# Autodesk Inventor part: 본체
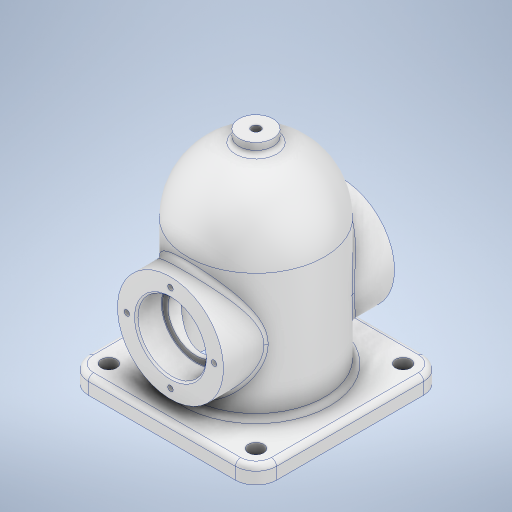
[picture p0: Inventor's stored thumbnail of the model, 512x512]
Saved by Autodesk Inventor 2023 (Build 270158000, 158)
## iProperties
Created: 2025-04
Part Number: 본체
Material: 알루미늄 6061
Document SubType Name: Modeling
Designer: User
Density: 2.7 g/cm^3
Appearance: 알루미늄 - 평지
Mass: 865.907 g
Surface Area: 800.754 cm^2
Volume: 320.706 cm^3
Author: User
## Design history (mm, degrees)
sketch "스케치1"
  geometry: C1 r 31 at (0, 0); 1 further point
  constraints: 1 centre point, 1 coincident
  dimensions: "d0" = 62 diameter of C1
extrude "돌출1" new body sketch "스케치1" stored distance "d1" = 100; taper "d2" = 0 deg
sketch "스케치9"
  geometry: C1 r 10 at (0, 0); 1 further point
  constraints: 1 centre point, 1 coincident
  dimensions: "d32" = 20 diameter of C1
extrude "돌출5" join sketch "스케치9" distance "d33" = 81; taper "d34" = 0 deg
sketch "스케치2"
  geometry: L1 (0, 0)-(0, -48); L2 (0, -48)-(40, -48); L3 (40, -48)-(40, 36); L4 (40, 36)-(0, 36); L5 (0, 36)-(0, 0); L6 (0, 76)-(0, 36); L7 (0, -74.457)-(0, 110.741) reference; C1 r 31 at (0, 0) reference; A1 r 40 centre (0, 36) between (40, 36) and (0, 76); 3 further points
  constraints: 12 end point, 4 perpendicular, 2 point on circle, 1 centre point, 1 coincident, 1 collinear, 1 point on line, 1 vertical
  dimensions: "d3" = 48 distance of L1.start L1.end; "d4" = 40 distance of L1.end L2.end; "d5" = 84 distance of L2.end L3.end
revolve "회전1" sketch "스케치2" stored, may be unused: angle "d6" = 90 deg
sketch "스케치7"
  geometry: L1 (-55, 55)-(55, 55); L2 (55, 55)-(55, -55); L3 (55, -55)-(-55, -55); L4 (-55, -55)-(-55, 55); L5 (-55, 55)-(55, -55); L6 (55, 55)-(-55, -55); 1 further point
  constraints: 12 end point, 2 midpoint, 2 parallel, 1 horizontal, 1 perpendicular
  dimensions: "d28" = 110 distance of L2.end L3.end; "d29" = 110 distance of L1.end L2.end
extrude "돌출4" join sketch "스케치7" distance "d30" = 10; taper "d31" = 0 deg
sketch "스케치3"
  geometry: L1 (40, -48)-(40, 36) reference; L2 (-40, -48)-(-40, 36) reference; L3 (32, -48)-(32, 36); L4 (-32, -48)-(-32, 36); L5 (40, -48)-(-40, -48) reference; L6 (0, -72.8)-(0, 100.8) reference; L7 (0, 68)-(0, -48); L8 (0, -48)-(32, -48); A1 r 40 centre (0, 36) between (40, 36) and (-40, 36) reference; A2 r 32 centre (0, 36) between (32, 36) and (-32, 36); 2 further points
  constraints: 8 end point, 3 point on circle, 3 point on line, 2 parallel, 1 centre point, 1 collinear, 1 midpoint
  dimensions: "d7" = 8 radial gap between concentric circles of A1 A2; "d8" = 8 distance between parallel lines of L1 L3; "d9" = 8 distance between parallel lines of L2 L4
revolve "회전2" sketch "스케치3" stored, may be unused: angle "d10" = 90 deg
sketch "스케치4"
  geometry: C1 r 20 at (0, 0); 1 further point
  constraints: 1 centre point, 1 coincident
  dimensions: "d11" = 40 diameter of C1
extrude "돌출2" cut sketch "스케치4" distance "d12" = 15; taper "d13" = 0 deg
sketch "스케치5"
  geometry: C1 r 16.5 at (0, 0); 1 further point
  constraints: 1 centre point, 1 coincident
  dimensions: "d14" = 33 diameter of C1
extrude "돌출3" cut sketch "스케치5" extent not by distance; stored distance "d15" = 0; taper "d16" = 0 deg
sketch "스케치6" dims "d17" = 51
  geometry: 3 further points
  constraints: 1 coincident, 1 horizontal alignment, 2 other
hole "구멍1" sketch "스케치6" at (-25.5, 0) diameter "d18" = 3.242; stored, may be unused: countersink angle "d22" = 90 deg, drill point angle "d24" = 118 deg; dims "d19" = 8, "d20" = 4, "d21" = 2, "d23" = 10
sketch "스케치8"
  geometry: 1 further point
sketch "스케치10"
  geometry: 2 further points
  constraints: 1 coincident
hole "구멍2" sketch "스케치10" at (0, 0) diameter "d35" = 5.1881; stored, may be unused: countersink angle "d39" = 90 deg, drill point angle "d41" = 118 deg; dims "d36" = 20, "d37" = 4, "d38" = 2, "d40" = 16
sketch "스케치11"
  geometry: L1 (-43, 43)-(43, 43); L2 (43, 43)-(43, -43); L3 (43, -43)-(-43, -43); L4 (-43, -43)-(-43, 43); L5 (-43, 43)-(43, -43); L6 (43, 43)-(-43, -43); C1 r 2.594 at (0, 0) reference; C2 r 4.5 at (-43, 43); C3 r 4.5 at (43, 43); C4 r 4.5 at (-43, -43); C5 r 4.5 at (43, -43); 1 further point
  constraints: 12 end point, 4 centre point, 4 coincident, 2 midpoint, 2 parallel, 1 horizontal, 1 perpendicular
  dimensions: "d42" = 86 distance of L2.end L3.end; "d43" = 86 distance of L1.end L2.end; "d44" = 9 diameter of C2; "d45" = 9 diameter of C3; "d46" = 9 diameter of C4; "d47" = 9 diameter of C5
extrude "돌출6" cut sketch "스케치11" extent not by distance; stored distance "d48" = 0; taper "d49" = 0 deg
node "작업 평면1"
sketch "스케치14"
  geometry: L1 (48, 55)-(48, -55) reference; L2 (73.8, 0)-(-106.8, 0) reference; 2 further points
  constraints: 1 point on line, 1 other
  dimensions: "d51" = 30 distance from line of L1 point (18, 0)
feature "엠보싱1" sketch "스케치14" dims "d52" = 0.5, "d53" = 0
fillet "모깎기1" dims "d54" = 12
fillet "모깎기2" dims "d55" = 0.3
chamfer "모따기1" distance "d56" = 1; stored, may be unused: second distance "d57" = 2, angle "d58" = 45 deg
fillet "모깎기3" dims "d59" = 3
feature "̖耀̘耀̚耀̜耀̞耀̠耀̢耀̤耀" dims "d0" = 62, "d1" = 100, "d2" = 0, "d3" = 48, "d4" = 40, "d5" = 84, "d6" = 90 deg, "d7" = 8, "d8" = 8, "d9" = 8, "d10" = 90 deg, "d11" = 40, "d12" = 15, "d13" = 0, "d14" = 33, "d15" = 0, "d16" = 0, "d17" = 51, "d18" = 3.242, "d19" = 8, "d20" = 4, "d21" = 2, "d22" = 90 deg, "d23" = 10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
node "솔리드1"
pattern_circular "원형 패턴1" dims angle "d26" = 360 deg
mirror "미러1"
feature "A9D066F2-1C7D-4E18-AEED-F7BC21143FA4" dims "d18" = 3.242, "d19" = 8, "d20" = 4, "d21" = 2, "d22" = 90 deg, "d23" = 10, "d24" = 118 deg
